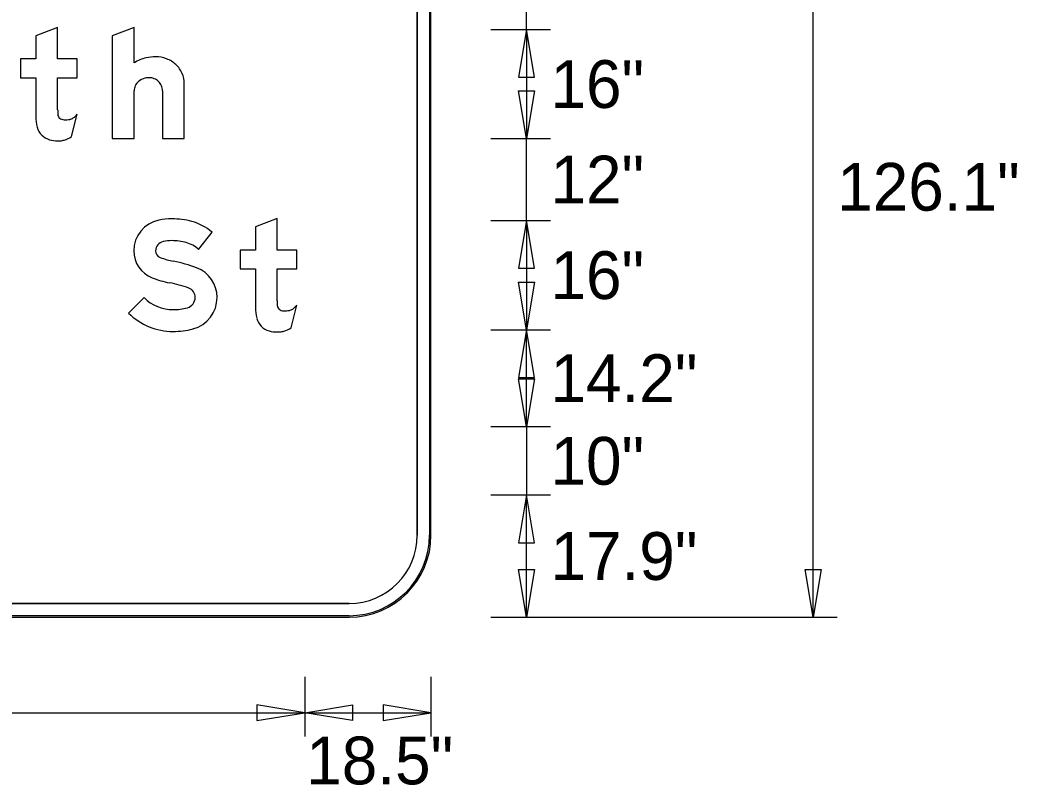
# Model space of a CAD drawing. Extents: x 2149961 to 2150220, y 145114 to 145240.
# Drawn here: x 2150207.96 to 2150220.13, y 145128.27 to 145137.61 of the extents above; entities that cross this region are included whole.
import ezdxf

# ---------------------------------------------------------------- set-up
doc = ezdxf.new("R2010")
doc.units = 0
for name, color, linetype in [('GSBWFILL', 7, 'Continuous'), ('GSCOLORFILL', 7, 'Continuous'), ('GSDIMS', 7, 'Continuous'), ('GSOUTLINE', 7, 'Continuous')]:
    doc.layers.add(name, color=color, linetype=linetype)

msp = doc.modelspace()

# ---------------------------------------------------------------- linework, layer by layer
at = {"layer": 'GSBWFILL'}
for p, q in [((2150212.806, 145145.817), (2150212.806, 145131.317)), ((2150212.973, 145131.317), (2150212.973, 145145.817)), ((2150208.585, 145136.183), (2150208.655, 145136.459)), ((2150211.265, 145133.85), (2150211.335, 145134.126)), ((2150211.973, 145130.483), (2150198.474, 145130.483)), ((2150198.474, 145130.317), (2150211.973, 145130.317))]:
    msp.add_line(p, q, dxfattribs=at)
for points in [[(2150208.415, 145136.512), (2150208.415, 145136.902), (2150208.655, 145136.902), (2150208.655, 145137.132), (2150208.415, 145137.132), (2150208.415, 145137.515), (2150208.149, 145137.414), (2150208.149, 145137.132), (2150207.962, 145137.132), (2150207.962, 145136.902), (2150208.149, 145136.902), (2150208.149, 145136.431)], [(2150209.349, 145137.083), (2150209.349, 145137.515), (2150209.082, 145137.412), (2150209.082, 145136.158), (2150209.349, 145136.158), (2150209.349, 145136.743)], [(2150209.695, 145136.743), (2150209.695, 145136.158), (2150209.962, 145136.158), (2150209.962, 145136.831)], [(2150211.095, 145134.178), (2150211.095, 145134.568), (2150211.335, 145134.568), (2150211.335, 145134.798), (2150211.095, 145134.798), (2150211.095, 145135.182), (2150210.829, 145135.08), (2150210.829, 145134.798), (2150210.642, 145134.798), (2150210.642, 145134.568), (2150210.829, 145134.568), (2150210.829, 145134.098)], [(2150210.135, 145134.806), (2150210.3, 145135.017)], [(2150209.47, 145134.217), (2150209.282, 145134.027)]]:
    msp.add_lwpolyline(points, dxfattribs=at)
for centre, radius, start, end in [((2150209.611, 145136.625), 0.533, 90, 102.6043), ((2150209.611, 145136.783), 0.375, 68.8636, 90), ((2150209.607, 145136.678), 0.48, 103.4695, 122.4943), ((2150209.62, 145136.806), 0.35, 46.975, 68.8636), ((2150209.634, 145136.821), 0.33, 23.9317, 46.975), ((2150209.656, 145136.831), 0.306, 0, 23.9317), ((2150209.488, 145136.743), 0.139, 154.5283, 180), ((2150209.509, 145136.733), 0.162, 131.0076, 154.5283), ((2150209.523, 145136.717), 0.183, 109.8074, 131.0076), ((2150209.532, 145136.692), 0.21, 90, 109.8074), ((2150209.532, 145136.734), 0.168, 68.0808, 90), ((2150209.533, 145136.738), 0.164, 45.8298, 68.0808), ((2150209.536, 145136.741), 0.159, 23.0928, 45.8298), ((2150209.541, 145136.743), 0.155, 0, 23.0928), ((2150211.973, 145131.317), 1, 270, 0), ((2150211.973, 145131.317), 0.833, 270, 0)]:
    msp.add_arc(centre, radius, start, end, dxfattribs=at)
for centre, major_axis, ratio, start_param, end_param in [((2150208.666, 145136.431), (0, 0.517), 0.99999, 1.570796, 1.830698), ((2150210.085, 145136.512), (0, 1.669), 0.99999, 1.570796, 1.606005), ((2150208.492, 145136.466), (0, 0.0767), 0.99999, 1.74085, 2.407828), ((2150208.48, 145136.59), (0, 0.219), 0.99999, 3.756278, 4.071638), ((2150208.375, 145136.354), (0, 0.217), 0.99999, 1.830698, 2.869526), ((2150208.494, 145136.469), (0, 0.0803), 0.99999, 2.407828, 3.141593), ((2150208.494, 145136.809), (0, 0.421), 0.99999, 3.141593, 3.310762), ((2150208.548, 145136.493), (0, 0.1), 0.99999, 3.310762, 3.756278), ((2150208.407, 145136.445), (0, 0.317), 0.99999, 3.427755, 3.738844), ((2150208.415, 145136.497), (0, 0.365), 0.99999, 2.869526, 3.141593), ((2150208.415, 145136.657), (0, 0.526), 0.99999, 3.141593, 3.205734), ((2150208.435, 145136.349), (0, 0.217), 0.99999, 3.205734, 3.427755), ((2150209.727, 145134.789), (0, 0.382), 0.999996, 0.202758, 1.570796), ((2150209.809, 145134.394), (0, 0.785), 0.999996, 0, 0.202758), ((2150209.809, 145134.216), (0, 0.963), 0.999996, 6.026234, 6.283185), ((2150209.898, 145134.556), (0, 0.611), 0.999996, 5.565152, 6.026234), ((2150209.727, 145134.789), (0, 0.115), 0.999996, 0.202758, 1.570796), ((2150209.809, 145134.394), (0, 0.519), 0.999996, 0, 0.202758), ((2150209.809, 145134.216), (0, 0.697), 0.999996, 6.026234, 6.283185), ((2150209.898, 145134.556), (0, 0.345), 0.999996, 5.523837, 6.026234), ((2150209.699, 145134.789), (0, 0.354), 0.999996, 1.570796, 2.761249), ((2150209.699, 145134.789), (0, 0.0872), 0.999996, 1.570796, 2.761249), ((2150209.99, 145135.516), (0, 0.87), 0.999996, 2.761249, 2.95744), ((2150209.533, 145133.065), (0, 1.623), 0.999996, 5.918637, 6.099033), ((2150209.974, 145134.219), (0, 0.388), 0.999996, 4.712389, 5.918637), ((2150209.99, 145135.516), (0, 1.137), 0.999996, 2.761249, 2.95744), ((2150209.533, 145133.065), (0, 1.357), 0.999996, 5.918637, 6.099033), ((2150209.974, 145134.219), (0, 0.122), 0.999996, 4.712389, 5.918637), ((2150209.825, 145134.575), (0, 0.504), 0.999996, 2.360607, 3.141593), ((2150209.966, 145134.219), (0, 0.129), 0.999996, 3.401517, 4.712389), ((2150209.966, 145134.219), (0, 0.396), 0.999996, 3.401517, 4.712389), ((2150212.765, 145134.178), (0, 1.669), 0.999994, 1.570796, 1.606005), ((2150211.172, 145134.133), (0, 0.0767), 0.999994, 1.74085, 2.407828), ((2150211.16, 145134.257), (0, 0.219), 0.999994, 3.756278, 4.071638), ((2150209.825, 145134.575), (0, 0.771), 0.999996, 2.360607, 3.141593), ((2150209.825, 145134.749), (0, 0.678), 0.999996, 3.141593, 3.401517), ((2150211.346, 145134.098), (0, 0.517), 0.999994, 1.570796, 1.830698), ((2150211.174, 145134.135), (0, 0.0803), 0.999994, 2.407828, 3.141593), ((2150211.174, 145134.476), (0, 0.421), 0.999994, 3.141593, 3.310762), ((2150211.228, 145134.159), (0, 0.1), 0.999994, 3.310762, 3.756278), ((2150211.055, 145134.02), (0, 0.217), 0.999994, 1.830698, 2.869526), ((2150209.825, 145134.749), (0, 0.945), 0.999996, 3.141593, 3.401517), ((2150211.095, 145134.163), (0, 0.365), 0.999994, 2.869526, 3.141593), ((2150211.095, 145134.324), (0, 0.526), 0.999994, 3.141593, 3.205734), ((2150211.115, 145134.016), (0, 0.217), 0.999994, 3.205734, 3.427755), ((2150211.087, 145134.112), (0, 0.317), 0.999994, 3.427755, 3.738844)]:
    msp.add_ellipse(centre, major_axis=major_axis, ratio=ratio, start_param=start_param, end_param=end_param, dxfattribs=at)
at = {"layer": 'GSCOLORFILL'}
for p, q in [((2150212.806, 145145.817), (2150212.806, 145131.317)), ((2150212.956, 145145.817), (2150212.956, 145131.317)), ((2150212.973, 145131.317), (2150212.973, 145145.817)), ((2150212.973, 145131.317), (2150212.973, 145145.817)), ((2150212.973, 145131.317), (2150212.973, 145145.817)), ((2150208.585, 145136.183), (2150208.655, 145136.459)), ((2150211.265, 145133.85), (2150211.335, 145134.126)), ((2150211.973, 145130.483), (2150198.474, 145130.483)), ((2150211.973, 145130.333), (2150198.473, 145130.333)), ((2150198.473, 145130.317), (2150211.973, 145130.317)), ((2150198.473, 145130.317), (2150211.973, 145130.317)), ((2150198.474, 145130.317), (2150211.973, 145130.317))]:
    msp.add_line(p, q, dxfattribs=at)
for points in [[(2150208.415, 145136.512), (2150208.415, 145136.902), (2150208.655, 145136.902), (2150208.655, 145137.132), (2150208.415, 145137.132), (2150208.415, 145137.515), (2150208.149, 145137.414), (2150208.149, 145137.132), (2150207.962, 145137.132), (2150207.962, 145136.902), (2150208.149, 145136.902), (2150208.149, 145136.431)], [(2150209.349, 145137.083), (2150209.349, 145137.515), (2150209.082, 145137.412), (2150209.082, 145136.158), (2150209.349, 145136.158), (2150209.349, 145136.743)], [(2150209.695, 145136.743), (2150209.695, 145136.158), (2150209.962, 145136.158), (2150209.962, 145136.831)], [(2150211.095, 145134.178), (2150211.095, 145134.568), (2150211.335, 145134.568), (2150211.335, 145134.798), (2150211.095, 145134.798), (2150211.095, 145135.182), (2150210.829, 145135.08), (2150210.829, 145134.798), (2150210.642, 145134.798), (2150210.642, 145134.568), (2150210.829, 145134.568), (2150210.829, 145134.098)], [(2150210.135, 145134.806), (2150210.3, 145135.017)], [(2150209.47, 145134.217), (2150209.282, 145134.027)]]:
    msp.add_lwpolyline(points, dxfattribs=at)
for centre, radius, start, end in [((2150209.611, 145136.625), 0.533, 90, 102.6043), ((2150209.611, 145136.783), 0.375, 68.8636, 90), ((2150209.607, 145136.678), 0.48, 103.4695, 122.4943), ((2150209.62, 145136.806), 0.35, 46.975, 68.8636), ((2150209.634, 145136.821), 0.33, 23.9317, 46.975), ((2150209.656, 145136.831), 0.306, 0, 23.9317), ((2150209.488, 145136.743), 0.139, 154.5283, 180), ((2150209.509, 145136.733), 0.162, 131.0076, 154.5283), ((2150209.523, 145136.717), 0.183, 109.8074, 131.0076), ((2150209.532, 145136.692), 0.21, 90, 109.8074), ((2150209.532, 145136.734), 0.168, 68.0808, 90), ((2150209.533, 145136.738), 0.164, 45.8298, 68.0808), ((2150209.536, 145136.741), 0.159, 23.0928, 45.8298), ((2150209.541, 145136.743), 0.155, 0, 23.0928), ((2150211.973, 145131.317), 1, 270, 0), ((2150211.973, 145131.317), 1, 270, 0), ((2150211.973, 145131.317), 0.833, 270, 0), ((2150211.973, 145131.317), 1, 270, 0), ((2150211.973, 145131.317), 0.983, 270, 0)]:
    msp.add_arc(centre, radius, start, end, dxfattribs=at)
for centre, major_axis, ratio, start_param, end_param in [((2150208.666, 145136.431), (0, 0.517), 0.99999, 1.570796, 1.830698), ((2150210.085, 145136.512), (0, 1.669), 0.99999, 1.570796, 1.606005), ((2150208.492, 145136.466), (0, 0.0767), 0.99999, 1.74085, 2.407828), ((2150208.48, 145136.59), (0, 0.219), 0.99999, 3.756278, 4.071638), ((2150208.375, 145136.354), (0, 0.217), 0.99999, 1.830698, 2.869526), ((2150208.494, 145136.469), (0, 0.0803), 0.99999, 2.407828, 3.141593), ((2150208.494, 145136.809), (0, 0.421), 0.99999, 3.141593, 3.310762), ((2150208.548, 145136.493), (0, 0.1), 0.99999, 3.310762, 3.756278), ((2150208.407, 145136.445), (0, 0.317), 0.99999, 3.427755, 3.738844), ((2150208.415, 145136.497), (0, 0.365), 0.99999, 2.869526, 3.141593), ((2150208.415, 145136.657), (0, 0.526), 0.99999, 3.141593, 3.205734), ((2150208.435, 145136.349), (0, 0.217), 0.99999, 3.205734, 3.427755), ((2150209.727, 145134.789), (0, 0.382), 0.999996, 0.202758, 1.570796), ((2150209.809, 145134.394), (0, 0.785), 0.999996, 0, 0.202758), ((2150209.809, 145134.216), (0, 0.963), 0.999996, 6.026234, 6.283185), ((2150209.898, 145134.556), (0, 0.611), 0.999996, 5.565152, 6.026234), ((2150209.727, 145134.789), (0, 0.115), 0.999996, 0.202758, 1.570796), ((2150209.809, 145134.394), (0, 0.519), 0.999996, 0, 0.202758), ((2150209.809, 145134.216), (0, 0.697), 0.999996, 6.026234, 6.283185), ((2150209.898, 145134.556), (0, 0.345), 0.999996, 5.523837, 6.026234), ((2150209.699, 145134.789), (0, 0.354), 0.999996, 1.570796, 2.761249), ((2150209.699, 145134.789), (0, 0.0872), 0.999996, 1.570796, 2.761249), ((2150209.99, 145135.516), (0, 0.87), 0.999996, 2.761249, 2.95744), ((2150209.533, 145133.065), (0, 1.623), 0.999996, 5.918637, 6.099033), ((2150209.974, 145134.219), (0, 0.388), 0.999996, 4.712389, 5.918637), ((2150209.99, 145135.516), (0, 1.137), 0.999996, 2.761249, 2.95744), ((2150209.533, 145133.065), (0, 1.357), 0.999996, 5.918637, 6.099033), ((2150209.974, 145134.219), (0, 0.122), 0.999996, 4.712389, 5.918637), ((2150209.825, 145134.575), (0, 0.504), 0.999996, 2.360607, 3.141593), ((2150209.966, 145134.219), (0, 0.129), 0.999996, 3.401517, 4.712389), ((2150209.966, 145134.219), (0, 0.396), 0.999996, 3.401517, 4.712389), ((2150212.765, 145134.178), (0, 1.669), 0.999994, 1.570796, 1.606005), ((2150211.172, 145134.133), (0, 0.0767), 0.999994, 1.74085, 2.407828), ((2150211.16, 145134.257), (0, 0.219), 0.999994, 3.756278, 4.071638), ((2150209.825, 145134.575), (0, 0.771), 0.999996, 2.360607, 3.141593), ((2150209.825, 145134.749), (0, 0.678), 0.999996, 3.141593, 3.401517), ((2150211.346, 145134.098), (0, 0.517), 0.999994, 1.570796, 1.830698), ((2150211.174, 145134.135), (0, 0.0803), 0.999994, 2.407828, 3.141593), ((2150211.174, 145134.476), (0, 0.421), 0.999994, 3.141593, 3.310762), ((2150211.228, 145134.159), (0, 0.1), 0.999994, 3.310762, 3.756278), ((2150211.055, 145134.02), (0, 0.217), 0.999994, 1.830698, 2.869526), ((2150209.825, 145134.749), (0, 0.945), 0.999996, 3.141593, 3.401517), ((2150211.095, 145134.163), (0, 0.365), 0.999994, 2.869526, 3.141593), ((2150211.095, 145134.324), (0, 0.526), 0.999994, 3.141593, 3.205734), ((2150211.115, 145134.016), (0, 0.217), 0.999994, 3.205734, 3.427755), ((2150211.087, 145134.112), (0, 0.317), 0.999994, 3.427755, 3.738844)]:
    msp.add_ellipse(centre, major_axis=major_axis, ratio=ratio, start_param=start_param, end_param=end_param, dxfattribs=at)
at = {"layer": 'GSDIMS'}
for p, q in [((2150217.639, 145130.317), (2150217.639, 145140.825)), ((2150214.139, 145137.492), (2150214.139, 145138.492)), ((2150213.702, 145137.492), (2150214.431, 145137.492)), ((2150213.702, 145137.492), (2150214.431, 145137.492)), ((2150214.139, 145137.492), (2150214.139, 145136.158)), ((2150213.702, 145136.158), (2150214.431, 145136.158)), ((2150213.702, 145136.158), (2150214.431, 145136.158)), ((2150214.139, 145135.158), (2150214.139, 145136.158)), ((2150213.702, 145135.158), (2150214.431, 145135.158)), ((2150213.702, 145135.158), (2150214.431, 145135.158)), ((2150214.139, 145135.158), (2150214.139, 145133.825)), ((2150213.702, 145133.825), (2150214.431, 145133.825)), ((2150213.702, 145133.825), (2150214.431, 145133.825)), ((2150214.139, 145132.642), (2150214.139, 145133.825)), ((2150213.702, 145132.642), (2150214.431, 145132.642)), ((2150213.702, 145132.642), (2150214.431, 145132.642)), ((2150214.139, 145132.642), (2150214.139, 145131.808)), ((2150213.702, 145131.808), (2150214.431, 145131.808)), ((2150213.702, 145131.808), (2150214.431, 145131.808)), ((2150214.139, 145130.317), (2150214.139, 145131.808)), ((2150213.702, 145130.317), (2150214.431, 145130.317)), ((2150213.702, 145130.317), (2150217.202, 145130.317)), ((2150217.202, 145130.317), (2150217.931, 145130.317)), ((2150211.431, 145129.587), (2150211.431, 145128.858)), ((2150211.431, 145129.587), (2150211.431, 145128.858)), ((2150212.973, 145129.587), (2150212.973, 145128.858)), ((2150212.973, 145129.587), (2150212.973, 145128.858)), ((2150199.014, 145129.15), (2150211.431, 145129.15)), ((2150211.431, 145129.15), (2150212.973, 145129.15))]:
    msp.add_line(p, q, dxfattribs=at)
for points in [[(2150214.139, 145137.492), (2150214.042, 145136.908), (2150214.237, 145136.908)], [(2150214.139, 145136.158), (2150214.042, 145136.742), (2150214.237, 145136.742)], [(2150214.139, 145135.158), (2150214.042, 145134.575), (2150214.237, 145134.575)], [(2150214.139, 145133.825), (2150214.042, 145134.408), (2150214.237, 145134.408)], [(2150214.139, 145133.825), (2150214.042, 145133.242), (2150214.237, 145133.242)], [(2150214.139, 145132.642), (2150214.042, 145133.225), (2150214.237, 145133.225)], [(2150214.139, 145131.808), (2150214.042, 145131.225), (2150214.237, 145131.225)], [(2150214.139, 145130.317), (2150214.042, 145130.9), (2150214.237, 145130.9)], [(2150217.639, 145130.317), (2150217.542, 145130.9), (2150217.737, 145130.9)], [(2150211.431, 145129.15), (2150210.848, 145129.247), (2150210.848, 145129.053)], [(2150211.431, 145129.15), (2150212.014, 145129.247), (2150212.014, 145129.053)], [(2150212.973, 145129.15), (2150212.389, 145129.247), (2150212.389, 145129.053)]]:
    msp.add_lwpolyline(points, close=True, dxfattribs=at)
at = {"layer": 'GSOUTLINE'}
for p, q in [((2150212.806, 145131.317), (2150212.806, 145145.817)), ((2150212.973, 145131.317), (2150212.973, 145145.817)), ((2150208.585, 145136.183), (2150208.655, 145136.459)), ((2150211.265, 145133.85), (2150211.335, 145134.126)), ((2150198.473, 145130.483), (2150211.973, 145130.483)), ((2150198.473, 145130.317), (2150211.973, 145130.317))]:
    msp.add_line(p, q, dxfattribs=at)
for points in [[(2150208.415, 145136.512), (2150208.415, 145136.902), (2150208.655, 145136.902), (2150208.655, 145137.132), (2150208.415, 145137.132), (2150208.415, 145137.515), (2150208.149, 145137.414), (2150208.149, 145137.132), (2150207.962, 145137.132), (2150207.962, 145136.902), (2150208.149, 145136.902), (2150208.149, 145136.431)], [(2150209.349, 145137.083), (2150209.349, 145137.515), (2150209.082, 145137.412), (2150209.082, 145136.158), (2150209.349, 145136.158), (2150209.349, 145136.743)], [(2150209.695, 145136.743), (2150209.695, 145136.158), (2150209.962, 145136.158), (2150209.962, 145136.831)], [(2150211.095, 145134.178), (2150211.095, 145134.568), (2150211.335, 145134.568), (2150211.335, 145134.798), (2150211.095, 145134.798), (2150211.095, 145135.182), (2150210.829, 145135.08), (2150210.829, 145134.798), (2150210.642, 145134.798), (2150210.642, 145134.568), (2150210.829, 145134.568), (2150210.829, 145134.098)], [(2150210.135, 145134.806), (2150210.3, 145135.017)], [(2150209.47, 145134.217), (2150209.282, 145134.027)]]:
    msp.add_lwpolyline(points, dxfattribs=at)
for centre, radius, start, end in [((2150209.611, 145136.625), 0.533, 90, 102.6043), ((2150209.611, 145136.783), 0.375, 68.8636, 90), ((2150209.607, 145136.678), 0.48, 103.4695, 122.4943), ((2150209.62, 145136.806), 0.35, 46.975, 68.8636), ((2150209.634, 145136.821), 0.33, 23.9317, 46.975), ((2150209.656, 145136.831), 0.306, 0, 23.9317), ((2150209.488, 145136.743), 0.139, 154.5283, 180), ((2150209.509, 145136.733), 0.162, 131.0076, 154.5283), ((2150209.523, 145136.717), 0.183, 109.8074, 131.0076), ((2150209.532, 145136.692), 0.21, 90, 109.8074), ((2150209.532, 145136.734), 0.168, 68.0808, 90), ((2150209.533, 145136.738), 0.164, 45.8298, 68.0808), ((2150209.536, 145136.741), 0.159, 23.0928, 45.8298), ((2150209.541, 145136.743), 0.155, 0, 23.0928), ((2150211.973, 145131.317), 1, 270, 0), ((2150211.973, 145131.317), 0.833, 270, 0)]:
    msp.add_arc(centre, radius, start, end, dxfattribs=at)
for centre, major_axis, ratio, start_param, end_param in [((2150208.666, 145136.431), (0, 0.517), 0.99999, 1.570796, 1.830698), ((2150210.085, 145136.512), (0, 1.669), 0.99999, 1.570796, 1.606005), ((2150208.492, 145136.466), (0, 0.0767), 0.99999, 1.74085, 2.407828), ((2150208.48, 145136.59), (0, 0.219), 0.99999, 3.756278, 4.071638), ((2150208.375, 145136.354), (0, 0.217), 0.99999, 1.830698, 2.869526), ((2150208.494, 145136.469), (0, 0.0803), 0.99999, 2.407828, 3.141593), ((2150208.494, 145136.809), (0, 0.421), 0.99999, 3.141593, 3.310762), ((2150208.548, 145136.493), (0, 0.1), 0.99999, 3.310762, 3.756278), ((2150208.407, 145136.445), (0, 0.317), 0.99999, 3.427755, 3.738844), ((2150208.415, 145136.497), (0, 0.365), 0.99999, 2.869526, 3.141593), ((2150208.415, 145136.657), (0, 0.526), 0.99999, 3.141593, 3.205734), ((2150208.435, 145136.349), (0, 0.217), 0.99999, 3.205734, 3.427755), ((2150209.727, 145134.789), (0, 0.382), 0.999996, 0.202758, 1.570796), ((2150209.809, 145134.394), (0, 0.785), 0.999996, 0, 0.202758), ((2150209.809, 145134.216), (0, 0.963), 0.999996, 6.026234, 6.283185), ((2150209.898, 145134.556), (0, 0.611), 0.999996, 5.565152, 6.026234), ((2150209.727, 145134.789), (0, 0.115), 0.999996, 0.202758, 1.570796), ((2150209.809, 145134.394), (0, 0.519), 0.999996, 0, 0.202758), ((2150209.809, 145134.216), (0, 0.697), 0.999996, 6.026234, 6.283185), ((2150209.898, 145134.556), (0, 0.345), 0.999996, 5.523837, 6.026234), ((2150209.699, 145134.789), (0, 0.354), 0.999996, 1.570796, 2.761249), ((2150209.699, 145134.789), (0, 0.0872), 0.999996, 1.570796, 2.761249), ((2150209.99, 145135.516), (0, 0.87), 0.999996, 2.761249, 2.95744), ((2150209.533, 145133.065), (0, 1.623), 0.999996, 5.918637, 6.099033), ((2150209.974, 145134.219), (0, 0.388), 0.999996, 4.712389, 5.918637), ((2150209.99, 145135.516), (0, 1.137), 0.999996, 2.761249, 2.95744), ((2150209.533, 145133.065), (0, 1.357), 0.999996, 5.918637, 6.099033), ((2150209.974, 145134.219), (0, 0.122), 0.999996, 4.712389, 5.918637), ((2150209.825, 145134.575), (0, 0.504), 0.999996, 2.360607, 3.141593), ((2150209.966, 145134.219), (0, 0.129), 0.999996, 3.401517, 4.712389), ((2150209.966, 145134.219), (0, 0.396), 0.999996, 3.401517, 4.712389), ((2150212.765, 145134.178), (0, 1.669), 0.999994, 1.570796, 1.606005), ((2150211.172, 145134.133), (0, 0.0767), 0.999994, 1.74085, 2.407828), ((2150211.16, 145134.257), (0, 0.219), 0.999994, 3.756278, 4.071638), ((2150209.825, 145134.575), (0, 0.771), 0.999996, 2.360607, 3.141593), ((2150209.825, 145134.749), (0, 0.678), 0.999996, 3.141593, 3.401517), ((2150211.346, 145134.098), (0, 0.517), 0.999994, 1.570796, 1.830698), ((2150211.174, 145134.135), (0, 0.0803), 0.999994, 2.407828, 3.141593), ((2150211.174, 145134.476), (0, 0.421), 0.999994, 3.141593, 3.310762), ((2150211.228, 145134.159), (0, 0.1), 0.999994, 3.310762, 3.756278), ((2150211.055, 145134.02), (0, 0.217), 0.999994, 1.830698, 2.869526), ((2150209.825, 145134.749), (0, 0.945), 0.999996, 3.141593, 3.401517), ((2150211.095, 145134.163), (0, 0.365), 0.999994, 2.869526, 3.141593), ((2150211.095, 145134.324), (0, 0.526), 0.999994, 3.141593, 3.205734), ((2150211.115, 145134.016), (0, 0.217), 0.999994, 3.205734, 3.427755), ((2150211.087, 145134.112), (0, 0.317), 0.999994, 3.427755, 3.738844)]:
    msp.add_ellipse(centre, major_axis=major_axis, ratio=ratio, start_param=start_param, end_param=end_param, dxfattribs=at)

# ---------------------------------------------------------------- texts
at = {"layer": 'GSDIMS'}
for s, p in [('16"', (2150214.431, 145136.533)), ('12"', (2150214.431, 145135.367)), ('126.1"', (2150217.931, 145135.279)), ('16"', (2150214.431, 145134.2)), ('14.2"', (2150214.431, 145132.942)), ('10"', (2150214.431, 145131.933)), ('17.9"', (2150214.431, 145130.771)), ('18.5"', (2150211.45, 145128.275))]:
    msp.add_text(s, height=0.5833, dxfattribs=at).set_placement(p)

doc.saveas('drawing.dxf')
